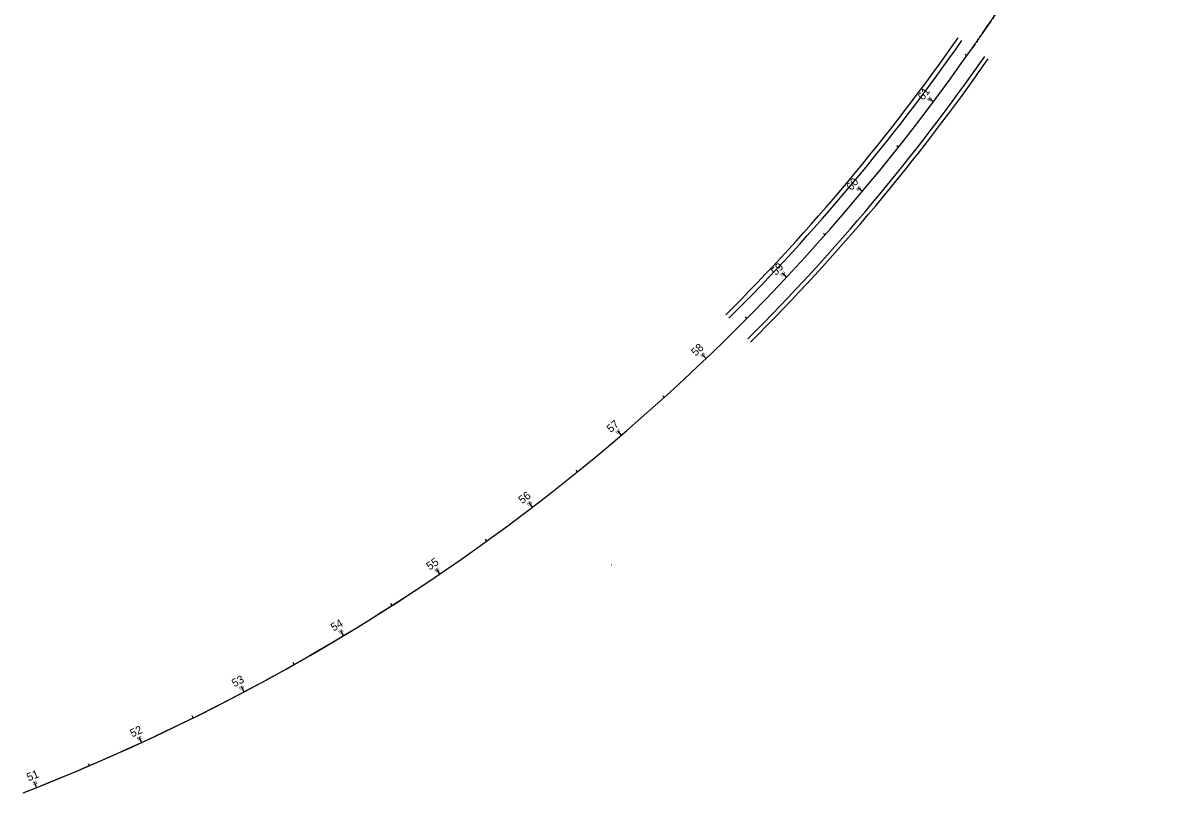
# Model space of a CAD drawing. Extents: x 1512289 to 1610162, y 552531 to 645498.
# Drawn here: x 1543673 to 1544685, y 587523 to 588196 of the extents above; entities that cross this region are included whole.
import ezdxf

# ---------------------------------------------------------------- set-up
doc = ezdxf.new("R2010")
doc.units = 0
for name, color, linetype in [('GE_X_CL_20', 7, 'Continuous'), ('GE_X_CL_50', 7, 'Continuous'), ('GK_Visualization', 7, 'Continuous'), ('MT_P_CL_Double_Solid', 7, 'Continuous'), ('PV_X_EOP', 7, 'Continuous'), ('PV_X_Shoulder', 7, 'Continuous')]:
    doc.layers.add(name, color=color, linetype=linetype)

msp = doc.modelspace()

# ---------------------------------------------------------------- linework, layer by layer
at = {"layer": 'GE_X_CL_20'}
for p, q in [((1544498.7, 588168), (1544497, 588169.1)), ((1544469.3, 588127.5), (1544467.7, 588128.7)), ((1544438.8, 588087.9), (1544437.2, 588089.2)), ((1544407.2, 588049.1), (1544405.7, 588050.4)), ((1544374.6, 588011.3), (1544373.1, 588012.6)), ((1544340.9, 587974.3), (1544339.5, 587975.7)), ((1544306.2, 587938.3), (1544304.8, 587939.7)), ((1544270.6, 587903.2), (1544269.2, 587904.7)), ((1544234, 587869.2), (1544232.6, 587870.6)), ((1544196.4, 587836.1), (1544195.1, 587837.7)), ((1544158, 587804.2), (1544156.8, 587805.7)), ((1544118.7, 587773.3), (1544117.5, 587774.8)), ((1544078.6, 587743.4), (1544077.4, 587745.1)), ((1544037.6, 587714.8), (1544036.5, 587716.4)), ((1543995.9, 587687.2), (1543994.8, 587688.9)), ((1543953.4, 587660.8), (1543952.4, 587662.6)), ((1543910.2, 587635.6), (1543909.2, 587637.4)), ((1543866.4, 587611.7), (1543865.4, 587613.4)), ((1543821.8, 587588.9), (1543821, 587590.7)), ((1543776.7, 587567.3), (1543775.9, 587569.2)), ((1543731, 587547.1), (1543730.2, 587548.9)), ((1543684.8, 587528.1), (1543684, 587529.9))]:
    msp.add_line(p, q, dxfattribs=at)
msp.add_arc((1543020.1, 589210.9), 1809.3, 291.1528, 325.0694, dxfattribs=at)
msp.add_spline([(1544684.9, 588474), (1544682.6, 588469.9), (1544680.3, 588465.8), (1544678, 588461.7), (1544675.6, 588457.6), (1544673.3, 588453.4), (1544671, 588449.3), (1544668.7, 588445.2), (1544666.3, 588441.1), (1544664, 588437), (1544661.7, 588432.8), (1544659.4, 588428.7), (1544657, 588424.6), (1544654.7, 588420.5), (1544652.4, 588416.4), (1544650, 588412.3), (1544647.7, 588408.2), (1544645.3, 588404), (1544643, 588399.9), (1544640.7, 588395.8), (1544638.3, 588391.7), (1544636, 588387.6), (1544633.6, 588383.5), (1544631.2, 588379.4), (1544628.9, 588375.3), (1544626.5, 588371.2), (1544624.1, 588367.1), (1544621.8, 588363), (1544619.4, 588358.9), (1544617, 588354.9), (1544614.6, 588350.8), (1544612.2, 588346.7), (1544609.9, 588342.6), (1544607.5, 588338.5), (1544605.1, 588334.5), (1544602.6, 588330.4), (1544600.2, 588326.3), (1544597.8, 588322.3), (1544595.4, 588318.2), (1544593, 588314.1), (1544590.5, 588310.1), (1544588.1, 588306), (1544585.6, 588302), (1544583.2, 588297.9), (1544580.7, 588293.9), (1544578.3, 588289.9), (1544575.8, 588285.8), (1544573.3, 588281.8), (1544570.8, 588277.8), (1544568.4, 588273.7), (1544565.9, 588269.7), (1544563.4, 588265.7), (1544560.8, 588261.7), (1544558.3, 588257.7), (1544555.8, 588253.7), (1544553.3, 588249.7), (1544550.7, 588245.7), (1544548.2, 588241.7), (1544545.6, 588237.8), (1544543, 588233.8), (1544540.5, 588229.8), (1544537.9, 588225.9), (1544535.3, 588221.9), (1544532.7, 588218), (1544530.1, 588214), (1544527.5, 588210.1), (1544524.8, 588206.1), (1544522.2, 588202.2), (1544519.6, 588198.3), (1544516.9, 588194.4), (1544514.2, 588190.5), (1544511.6, 588186.6), (1544508.9, 588182.7), (1544506.2, 588178.8), (1544503.5, 588174.9)], degree=3, dxfattribs=at)
at = {"layer": 'GE_X_CL_50'}
for p, q in [((1544469.3, 588127.5), (1544465.3, 588130.5)), ((1544407.2, 588049.1), (1544403.4, 588052.4)), ((1544340.9, 587974.3), (1544337.3, 587977.7)), ((1544270.6, 587903.2), (1544267.1, 587906.8)), ((1544196.4, 587836.1), (1544193.2, 587839.9)), ((1544118.7, 587773.3), (1544115.7, 587777.2)), ((1544037.6, 587714.8), (1544034.8, 587718.9)), ((1543953.4, 587660.8), (1543950.8, 587665.1)), ((1543866.4, 587611.7), (1543864, 587616.1)), ((1543776.7, 587567.3), (1543774.6, 587571.9)), ((1543684.8, 587528.1), (1543682.9, 587532.7))]:
    msp.add_line(p, q, dxfattribs=at)
msp.add_arc((1543020.1, 589210.9), 1809.3, 291.1528, 325.0694, dxfattribs=at)
msp.add_spline([(1544684.9, 588474), (1544682.6, 588469.9), (1544680.3, 588465.8), (1544678, 588461.7), (1544675.6, 588457.6), (1544673.3, 588453.4), (1544671, 588449.3), (1544668.7, 588445.2), (1544666.3, 588441.1), (1544664, 588437), (1544661.7, 588432.8), (1544659.4, 588428.7), (1544657, 588424.6), (1544654.7, 588420.5), (1544652.4, 588416.4), (1544650, 588412.3), (1544647.7, 588408.2), (1544645.3, 588404), (1544643, 588399.9), (1544640.7, 588395.8), (1544638.3, 588391.7), (1544636, 588387.6), (1544633.6, 588383.5), (1544631.2, 588379.4), (1544628.9, 588375.3), (1544626.5, 588371.2), (1544624.1, 588367.1), (1544621.8, 588363), (1544619.4, 588358.9), (1544617, 588354.9), (1544614.6, 588350.8), (1544612.2, 588346.7), (1544609.9, 588342.6), (1544607.5, 588338.5), (1544605.1, 588334.5), (1544602.6, 588330.4), (1544600.2, 588326.3), (1544597.8, 588322.3), (1544595.4, 588318.2), (1544593, 588314.1), (1544590.5, 588310.1), (1544588.1, 588306), (1544585.6, 588302), (1544583.2, 588297.9), (1544580.7, 588293.9), (1544578.3, 588289.9), (1544575.8, 588285.8), (1544573.3, 588281.8), (1544570.8, 588277.8), (1544568.4, 588273.7), (1544565.9, 588269.7), (1544563.4, 588265.7), (1544560.8, 588261.7), (1544558.3, 588257.7), (1544555.8, 588253.7), (1544553.3, 588249.7), (1544550.7, 588245.7), (1544548.2, 588241.7), (1544545.6, 588237.8), (1544543, 588233.8), (1544540.5, 588229.8), (1544537.9, 588225.9), (1544535.3, 588221.9), (1544532.7, 588218), (1544530.1, 588214), (1544527.5, 588210.1), (1544524.8, 588206.1), (1544522.2, 588202.2), (1544519.6, 588198.3), (1544516.9, 588194.4), (1544514.2, 588190.5), (1544511.6, 588186.6), (1544508.9, 588182.7), (1544506.2, 588178.8), (1544503.5, 588174.9)], degree=3, dxfattribs=at)
at = {"layer": 'GK_Visualization'}
for p, q in [((1544503.6, 588174.9), (1544503.4, 588174.9)), ((1544503.6, 588174.9), (1544503.4, 588174.9)), ((1544503.5, 588175), (1544503.5, 588174.8)), ((1544503.5, 588175), (1544503.5, 588174.8)), ((1544187.7, 587722.6), (1544187.5, 587722.6)), ((1544187.6, 587722.6), (1544187.6, 587722.5)), ((1543673, 587523.5), (1543673, 587523.4)), ((1543673.1, 587523.5), (1543673, 587523.5)), ((1543673.1, 587523.5), (1543673, 587523.5))]:
    msp.add_line(p, q, dxfattribs=at)
msp.add_arc((1543020.1, 589210.9), 1809.3, 291.1528, 325.0694, dxfattribs=at)
msp.add_arc((1543020.1, 589210.9), 1809.3, 291.1528, 325.0694, dxfattribs=at)
msp.add_spline([(1544503.5, 588174.9), (1544506.2, 588178.8), (1544508.9, 588182.7), (1544511.6, 588186.6), (1544514.2, 588190.5), (1544516.9, 588194.4), (1544519.6, 588198.3), (1544522.2, 588202.2), (1544524.8, 588206.1), (1544527.5, 588210.1), (1544530.1, 588214), (1544532.7, 588218), (1544535.3, 588221.9), (1544537.9, 588225.9), (1544540.5, 588229.8), (1544543, 588233.8), (1544545.6, 588237.8), (1544548.2, 588241.7), (1544550.7, 588245.7), (1544553.3, 588249.7), (1544555.8, 588253.7), (1544558.3, 588257.7), (1544560.8, 588261.7), (1544563.4, 588265.7), (1544565.9, 588269.7), (1544568.4, 588273.7), (1544570.8, 588277.8), (1544573.3, 588281.8), (1544575.8, 588285.8), (1544578.3, 588289.9), (1544580.7, 588293.9), (1544583.2, 588297.9), (1544585.6, 588302), (1544588.1, 588306), (1544590.5, 588310.1), (1544593, 588314.1), (1544595.4, 588318.2), (1544597.8, 588322.3), (1544600.2, 588326.3), (1544602.6, 588330.4), (1544605.1, 588334.5), (1544607.5, 588338.5), (1544609.9, 588342.6), (1544612.2, 588346.7), (1544614.6, 588350.8), (1544617, 588354.9), (1544619.4, 588358.9), (1544621.8, 588363), (1544624.1, 588367.1), (1544626.5, 588371.2), (1544628.9, 588375.3), (1544631.2, 588379.4), (1544633.6, 588383.5), (1544636, 588387.6), (1544638.3, 588391.7), (1544640.7, 588395.8), (1544643, 588399.9), (1544645.3, 588404), (1544647.7, 588408.2), (1544650, 588412.3), (1544652.4, 588416.4), (1544654.7, 588420.5), (1544657, 588424.6), (1544659.4, 588428.7), (1544661.7, 588432.8), (1544664, 588437), (1544666.3, 588441.1), (1544668.7, 588445.2), (1544671, 588449.3), (1544673.3, 588453.4), (1544675.6, 588457.6), (1544678, 588461.7), (1544680.3, 588465.8), (1544682.6, 588469.9), (1544684.9, 588474)], degree=3, dxfattribs=at)
msp.add_spline([(1544503.5, 588174.9), (1544506.2, 588178.8), (1544508.9, 588182.7), (1544511.6, 588186.6), (1544514.2, 588190.5), (1544516.9, 588194.4), (1544519.6, 588198.3), (1544522.2, 588202.2), (1544524.8, 588206.1), (1544527.5, 588210.1), (1544530.1, 588214), (1544532.7, 588218), (1544535.3, 588221.9), (1544537.9, 588225.9), (1544540.5, 588229.8), (1544543, 588233.8), (1544545.6, 588237.8), (1544548.2, 588241.7), (1544550.7, 588245.7), (1544553.3, 588249.7), (1544555.8, 588253.7), (1544558.3, 588257.7), (1544560.8, 588261.7), (1544563.4, 588265.7), (1544565.9, 588269.7), (1544568.4, 588273.7), (1544570.8, 588277.8), (1544573.3, 588281.8), (1544575.8, 588285.8), (1544578.3, 588289.9), (1544580.7, 588293.9), (1544583.2, 588297.9), (1544585.6, 588302), (1544588.1, 588306), (1544590.5, 588310.1), (1544593, 588314.1), (1544595.4, 588318.2), (1544597.8, 588322.3), (1544600.2, 588326.3), (1544602.6, 588330.4), (1544605.1, 588334.5), (1544607.5, 588338.5), (1544609.9, 588342.6), (1544612.2, 588346.7), (1544614.6, 588350.8), (1544617, 588354.9), (1544619.4, 588358.9), (1544621.8, 588363), (1544624.1, 588367.1), (1544626.5, 588371.2), (1544628.9, 588375.3), (1544631.2, 588379.4), (1544633.6, 588383.5), (1544636, 588387.6), (1544638.3, 588391.7), (1544640.7, 588395.8), (1544643, 588399.9), (1544645.3, 588404), (1544647.7, 588408.2), (1544650, 588412.3), (1544652.4, 588416.4), (1544654.7, 588420.5), (1544657, 588424.6), (1544659.4, 588428.7), (1544661.7, 588432.8), (1544664, 588437), (1544666.3, 588441.1), (1544668.7, 588445.2), (1544671, 588449.3), (1544673.3, 588453.4), (1544675.6, 588457.6), (1544678, 588461.7), (1544680.3, 588465.8), (1544682.6, 588469.9), (1544684.9, 588474)], degree=3, dxfattribs=at)
at = {"layer": 'MT_P_CL_Double_Solid'}
msp.add_arc((1543020.1, 589210.9), 1809.3, 291.1528, 303.4274, dxfattribs=at)
at = {"layer": 'PV_X_EOP'}
for radius, start in [(1798.1, 314.9502), (1822.5, 314.9168)]:
    msp.add_arc((1543020.1, 589210.9), radius, start, 325.0694, dxfattribs=at)
at = {"layer": 'PV_X_Shoulder'}
for radius, start in [(1794, 314.9558), (1826.2, 314.9118)]:
    msp.add_arc((1543020.1, 589210.9), radius, start, 325.0694, dxfattribs=at)

# ---------------------------------------------------------------- texts
at = {"layer": 'GE_X_CL_20'}
for s, rotation, p in [('61', 53.219, (1544465.8, 588127.9)), ('60', 50.0524, (1544403.4, 588049.3)), ('59', 46.8857, (1544337.2, 587974.7)), ('58', 43.719, (1544266.9, 587903.8)), ('57', 40.5524, (1544192.7, 587836.9)), ('56', 37.3857, (1544115.1, 587774.2)), ('55', 34.219, (1544034, 587716)), ('54', 31.0524, (1543949.9, 587662.2)), ('53', 27.8857, (1543862.9, 587613.2)), ('52', 24.719, (1543773.4, 587569.1)), ('51', 21.5523, (1543682, 587530.2))]:
    msp.add_text(s, height=2.8, rotation=rotation, dxfattribs=at).set_placement(p)
at = {"layer": 'GE_X_CL_50'}
for s, rotation, p in [('61', 53.219, (1544460.5, 588128.4)), ('60', 50.0524, (1544397.7, 588049.5)), ('59', 46.8857, (1544331.6, 587975.3)), ('58', 43.719, (1544261.4, 587904.8)), ('57', 40.5524, (1544187.1, 587838)), ('56', 37.3857, (1544109.6, 587775.7)), ('55', 34.219, (1544028.7, 587717.8)), ('54', 31.0524, (1543944.7, 587664.4)), ('53', 27.8857, (1543857.8, 587615.6)), ('52', 24.719, (1543768.5, 587571.8)), ('51', 21.5523, (1543677.8, 587533.4))]:
    msp.add_text(s, height=7, rotation=rotation, dxfattribs=at).set_placement(p)

doc.saveas('drawing.dxf')
